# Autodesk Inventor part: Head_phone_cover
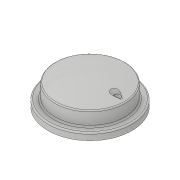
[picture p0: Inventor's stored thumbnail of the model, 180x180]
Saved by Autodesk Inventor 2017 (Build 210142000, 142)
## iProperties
Created: 2016-09
Part Number: Head_phone_cover
Material: Generic
Document SubType Name: Modeling
Designer: Gaurav
Density: 1 g/cm^3
Appearance: Default
Author: Gaurav
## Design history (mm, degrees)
sketch "Sketch1"
  geometry: L1 (-30, 0)-(-30, 5); L2 (-30, 5)-(-25, 5); L3 (-25, 5)-(-25, 15); L4 (0, 0)-(0, 46.091); L5 (-30, 0)-(0, 0); A1 r 60 centre (0, -39.544) between (0, 20.456) and (-25, 15)
  constraints: 10 end point, 2 perpendicular, 2 point on circle, 2 vertical, 1 centre point, 1 horizontal, 1 point on line
  dimensions: "d0" = 5 distance of L1.start L1.end; "d1" = 5 distance of L1.end L2.end; "d2" = 10 distance of L2.end L3.end; "d4" = 60 radius of A1
revolve "Revolution1" sketch "Sketch1" stored, may be unused: angle "d5" = 90 deg
fillet "Fillet1" dims "d6" = 1
workplane "Work Plane2"
  workplane "Work Plane1"
sketch "Sketch2"
  geometry: L1 (15.341, 0)-(24.407, 0); 7 further points
  constraints: 2 end point, 8 other
sketch "Sketch3"
  geometry: L1 (23.53, 0)-(14.512, 6.555); L2 (14.512, 6.555)-(14.512, 0); L3 (23.53, 0)-(14.512, -6.555); L4 (14.512, -6.555)-(14.512, 0); 1 further point
  constraints: 1 vertical, 6 other
loft "Loft1" sketch "Sketch2", "Sketch3" dims "d9" = 0, "d10" = 90 deg, "d11" = 10, "d12" = 90 deg
sketch "Sketch5"
  geometry: L1 (22.072, 16)-(17.611, 16); A1 r 0.74 centre (18.351, 15.972) between (18.372, 16.712) and (17.611, 16); A2 r 12.811 centre (18.018, 3.906) between (21.973, 16.091) and (18.372, 16.712); A3 r 0.161 centre (21.924, 15.938) between (22.072, 16) and (21.973, 16.091); 1 further point
  constraints: 6 point on circle, 3 centre point, 2 end point, 2 tangent, 1 horizontal
revolve "Revolution2" sketch "Sketch5" stored, may be unused: angle "d13" = 180 deg
shell "Shell1" dims "d14" = 1
body "Solid1"
other parameters: "d7" = -16, "d8" = -5
